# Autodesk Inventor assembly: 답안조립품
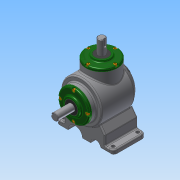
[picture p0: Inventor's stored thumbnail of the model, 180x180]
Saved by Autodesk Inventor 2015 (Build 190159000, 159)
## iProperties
Created: 2018-08
Part Number: 답안조립품
Document SubType Name: Assembly
Designer: user
Author: user
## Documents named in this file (14)
- C:\Users\user\Desktop\480807V1003\답안조립품.iam
- C:\Users\user\Desktop\480807V1003\본체.ipt
- C:\Users\user\Desktop\480807V1003\커버.ipt
- C:\Users\user\Desktop\480807V1003\오일실 17 32 8.ipt
- C:\Users\user\Desktop\480807V1003\베어링 6203.ipt
- C:\Users\user\Desktop\480807V1003\메인 축.ipt
- 메인 축.ipt
- C:\Users\user\Desktop\480807V1003\메인 베벨기어.ipt
- C:\Users\user\Desktop\480807V1003\키 5x5.ipt
- C:\Users\user\Desktop\480807V1003\서브 축.ipt
- 서브 축.ipt
- C:\Users\user\Desktop\480807V1003\키 4x4.ipt
- C:\Users\user\Desktop\480807V1003\볼트 M4.ipt
- C:\Users\user\Desktop\480807V1003\서브 베벨기어.ipt
